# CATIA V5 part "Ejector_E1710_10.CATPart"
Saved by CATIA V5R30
Part number: Vyhazovac_2.5x160_8
Nomenclature: E1710/2.5x160
Description: MEUSBURGER
Property "Material": "1.221"
Publications: "__DrillHole", "Base"
Bounding box of the stored display mesh (mm): x -2.499 to 2.499, y -2.499 to 2.499, z 0 to 154.3
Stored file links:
  E:\Bakalarka\Model\Forma_v7\Ejector_E1710_10.CATPart
  E:\dev\MoldDesign\intel_a\startup\components\MoldCatalog\Ejector\Meusburger\Ejector_E1710\TableE1710.txt
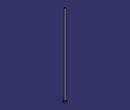
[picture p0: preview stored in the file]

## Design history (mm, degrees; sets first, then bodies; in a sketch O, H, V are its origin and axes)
Parameters
  Ref = "E1710/2.5x160" {design table}
  D1 = 2.5 mm {design table}
  D3 = 5 mm {design table}
  L = 160 mm {design table}
  L3 = 2 mm {design table}
  R = 0.3 mm {design table}
  k_d3 = 6 mm {design table}
  k_d1 = 2.7 mm {design table}
  k_F = 0.3 mm {design table}
  kl = 17 mm {design table}
  Mat = "1.221" {design table}
  HeatTreat = "ISO6751" {design table}
  Offset_Parting = 10 mm
  Anti_Rotation = "Normal"
  Anti_Rotation_D = 1.55 mm
  Anti_Rotation_D_Icut = 1.55 mm
  Add_Length_L = 0.0877 mm
  Add_Length_D3 = 0 mm
  SupplierRef = "Meusburger 2017"
  BmpRef = "F_MldEjectorD1"
  DrillHole_Length = 225 mm
  ValidationTest = false
  Anti_Rotation_D_min = 1.55 mm {= OffSet_D1 /2}
  Anti_Rotation_D_max = 2.425 mm {= D3/2-0.075mm}
  Anti_Rotation_D_ref = 1.55 mm {= Anti_Rotation_D}
  Anti_Rotation_D_Icut_ref = 1.55 mm {= Anti_Rotation_D_Icut}
  Anti_Rotation_Ref_Icut = 2.3246 mm
  Offset_L = 20 mm
  D = 2.5 mm {= D1}
  OffSet_D1 = 3.1 mm {= D1+2*R}
  OffSet_D3 = 6 mm {= D3+1mm}
  XG_Split = 60 mm
  YG_Split = -57.5 mm
  ZG_Split = -198 mm
  DirX_Split = 0 mm
  DirY_Split = 0 mm
  DirZ_Split = 1 mm
Set1 "BaseBody"
  Point1 "Base": (0, 0, 0)
  Plane1: type Offset, RefPlane xy-plane, Offset 225 {= DrillHole_Length}, reversed
  Sketch1 "Sketch.2" on xy-plane, origin (0, 0, 0), H (1, 0, 0), V (0, 1, 0)
    point P1 (-0.46, 1.1623)
    point P2 (0.46, 1.1623)
    construction line L1 (-0.46, 1.1623) -> (0.46, 1.1623)
    point P3 (0.46, -1.1623)
    line L2 (0.46, -1.1623) -> (0.46, 1.1623)
    point P4 (-0.46, -1.1623)
    construction line L3 (0.46, -1.1623) -> (-0.46, -1.1623)
    line L4 (-0.46, 1.1623) -> (-0.46, -1.1623)
    point P5 (-0.21, 1.1623)
    arc A1 centre (-0.21, 1.1623) radius 0.25 from (-0.21, 1.4123) to (-0.46, 1.1623) ccw
    point P7 (0.21, 1.1623)
    point P8 (0.21, 1.4123)
    arc A2 centre (0.21, 1.1623) radius 0.25 from (0.46, 1.1623) to (0.21, 1.4123) ccw
    line L5 (-0.21, 1.4123) -> (0.21, 1.4123)
    point P9 (-0.46, -1.1623)
    arc A3 centre (-0.21, -1.1623) radius 0.25 from (-0.46, -1.1623) to (-0.21, -1.4123) ccw
    point P11 (0.21, -1.4123)
    line L6 (-0.21, -1.4123) -> (0.21, -1.4123)
    point P12 (0.46, -1.1623)
    arc A4 centre (0.21, -1.1623) radius 0.25 from (0.21, -1.4123) to (0.46, -1.1623) ccw
    point P14 (-0.46, 1.1623)
    point P15 (-0.46, -1.1623)
    point P16 (0.46, 1.1623)
    point P17 (0.46, -1.1623)
    reference projected circle E1 centre (0, 0) radius 1.25 from edge [face of Shaft1 from Sketch2.L3 | face of Shaft1 from Sketch2.L4]
    reference projected circle E2 centre (0, 0) radius 1.25 from edge [face of Shaft1 from Sketch2.L3 | face of Shaft1 from Sketch2.L4]
    reference projected circle E3 centre (0, 0) radius 1.25 from edge [face of Shaft1 from Sketch2.L3 | face of Shaft1 from Sketch2.L4]
    reference projected circle E4 centre (0, 0) radius 1.25 from edge [face of Shaft1 from Sketch2.L3 | face of Shaft1 from Sketch2.L4]
    point P18 (-0.46, -1.1623)
    point P19 (-0.21, -1.4123)
    point P20 (0.21, -1.4123)
    point P21 (0.46, -1.1623)
    point P22 (-0.21, -1.4123)
    point P23 (0.21, -1.4123)
    distance P14 P15 = 2.3246 (reference)
    distance P16 P17 = 2.3246 (reference)
    distance L1 P14 = 0 (reference)
    radius A1 = 1.25
    distance L4 V = 1.56
    distance L2 V = 2.435
    distance L5 L6 = 5
    horizontal: L1 H, L3 H, L5 H
    vertical: L2 V, L4 V
    coincidence: P5 L1, P7 L1, P3 P12, P14 L4, P15 L4, P16 L2, P17 L2, P14 E1, P15 E2, P16 E3, P17 E4, P3 P21, P4 P18, P20 P23, P19 P22
    tangency: A1 L4, A2 L2, A2 L5, A1 L5
    symmetry: P1 P9 H, A1 A3 H, P8 P11 H, L5 L6 H, P2 P12 H, A2 A4 H
  DatumSurface1
Body1 "PartBody" (main body)
  Sketch2 "Sketch.1" on zx-plane, origin (0, 0, 0), H (-1, 0, 0), V (0, 0, 1)
    point P1 (0, 160)
    line L1 (1.25, 160) -> (0, 160)
    line L2 (1.25, 2) -> (1.25, 160)
    line L3 (2.5, 2) -> (1.25, 2)
    line L4 (2.5, 0) -> (2.5, 2)
    point P5 (0, 0)
    line L5 (0, 0) -> (2.5, 0)
    point P6 (0, 160)
    axis line L6 (0, 160) -> (0, 0)
    point P7 (0, 0)
    point P8 (1.25, 2)
    point P9 (1.25, 2)
    line L7 (0, 160) -> (0, 0)
    distance L5 L3 = 2 {= L3}
    distance L5 L1 = 160 {= L}
    distance L2 L6 = 1.25 {= D1 /2}
    distance L4 L6 = 2.5 {= D3 /2}
    coincidence: L6 P5, P1 L6, L5 H, L6 V, P7 O, P6 P1, P8 P9
    vertical: L2 V, L7 V
    horizontal: L1 H
  Shaft1 "Shaft.1": profile Sketch2, axis Sketch2.L6, angle 360
  Pocket1 "Pocket.1": profile Sketch1, direction (0, 0, 1), length 3, outer side, deactivated
  Pocket2 "Pocket.2": profile Sketch1, direction (0, 0, 1), length 3, outer side, deactivated
  Fillet1: radius 0.3 {= R}, on edge [face of Shaft1 from Sketch2.L2 | face of Shaft1 from Sketch2.L3]
  Pocket3: profile face of Shaft1 from Sketch2.L1, direction along face of Shaft1 from Sketch2.L1 reversed, up to face of DatumSurface1
Body2 "__DrillHole"
  Sketch3 "Sketch.3" on face of Shaft1, origin (0, 0, 0), H (1, 0, 0), V (0, -1, 0)
    point P1 (0, 0)
    reference projected point E1 (0, 0) from Point1
    coincidence: E1 P1
  Hole1 "Hole.1": placed by Sketch3, at (0, 0, 0) direction (0, 0, 1), diameter 3.1 {= OffSet_D1}, depth 140 {= L-Offset_L}
  Sketch4 "Sketch.4" on face of Shaft1, origin (0, 0, 0), H (1, 0, 0), V (0, -1, 0)
    point P1 (0, 0)
    reference projected point E1 (0, 0) from Point1
    coincidence: E1 P1
  Hole2 "Hole.2": placed by Sketch4, at (0, 0, 0) direction (0, 0, 1), diameter 2.5 {= D1}, depth 160 {= L}
  Sketch5 "Sketch.5" on face of Shaft1 from Sketch2.L3, origin (0, 0, 2), H (1, 0, 0), V (0, 1, 0)
    point P1 (0, 0)
    reference projected point E1 (0, 0) from Point1
    coincidence: E1 P1
  Hole3 "Hole.3": placed by Sketch5, at (0, 0, 2) direction (0, 0, -1), diameter 6 {= OffSet_D3}, depth 227 {= L3 +DrillHole_Length}
  Chamfer1: length 0.3 {= k_F}, angle 45, on edge [face of Hole1 | face of Hole3]
  Body3 "__Body.1"
    Pocket4 "Pocket.3": profile Sketch1, direction (0, 0, -1), length 225, opposite side length 2, deactivated
  Assemble1: tool Body3
  Chamfer2: length 0.3 {= k_F}, angle 45, on edge [start face of Pocket4 | face of Hole1], deactivated
  Body4 "__Body.2"
    Pocket5 "Pocket.4": profile Sketch1, direction (0, 0, -1), length 225, opposite side length 2, deactivated
  Assemble2: tool Body4
  Chamfer3: length 0.3 {= k_F}, angle 45, on edge [start face of Pocket5 | face of Hole1], deactivated
Relations
  design table "TableE1710", configuration 134, drives Ref, D1, D3, L, L3, R, k_d3, k_d1, k_F, kl, Mat, HeatTreat
  Offset_L = 20mm (deactivated)
  rule "Cut_Head_rule":
    let sketch_cut (length)
    let PartBody_Pocket_Sketch (Boolean)
    let I_PartBody_Pocket (Boolean)
    let D_PartBody_Pocket (Boolean)
    let N_DrillHole_Hole (Boolean)
    let N_DrillHole_Hole_Sketch (Boolean)
    let I_DrillHole_Pocket (Boolean)
    let D_DrillHole_Pocket (Boolean)
    /* --------------------------------------------------------------------------------------*/
    if Anti_Rotation =="Normal"
    {
    	sketch_cut=Anti_Rotation_D_max
    	PartBody_Pocket_Sketch = false
    	I_PartBody_Pocket = false
    	D_PartBody_Pocket = false
    	N_DrillHole_Hole = true
    	N_DrillHole_Hole_Sketch = true
    	I_DrillHole_Pocket = false
    	D_DrillHole_Pocket = false
    	Chamfer1.Activity= true
    	Chamfer2.Activity= false
    	Chamfer3.Activity= false
    }
    if Anti_Rotation == "I_Cut"
    {
    	sketch_cut=Anti_Rotation_D_Icut_ref
    	PartBody_Pocket_Sketch = true
    	I_PartBody_Pocket = true
    	D_PartBody_Pocket = false
    	N_DrillHole_Hole = false
    	N_DrillHole_Hole_Sketch = false
    	I_DrillHole_Pocket = true
    	D_DrillHole_Pocket = false
    	Chamfer1.Activity= false
    	Chamfer2.Activity= true
    	Chamfer3.Activity= false
    }
    if Anti_Rotation =="D_Cut"
    {
    	sketch_cut=Anti_Rotation_D_max
    	PartBody_Pocket_Sketch = true
    	I_PartBody_Pocket = false
    	D_PartBody_Pocket = true
    	N_DrillHole_Hole = false
    	N_DrillHole_Hole_Sketch = false
    	I_DrillHole_Pocket = false
    	D_DrillHole_Pocket = true
    	Chamfer1.Activity= false
    	Chamfer2.Activity= false
    	Chamfer3.Activity= true
    }
    /* --------------------------------------------------------------------------------------*/
    Sketch1.distance(L2 V) = sketch_cut+0.01mm
    Sketch1.distance(L4 V) =Anti_Rotation_D_ref+0.01mm
    Sketch1.radius(A1) =D/2
    Pocket4.FirstLimit.Depth = DrillHole_Length
    Pocket5.FirstLimit.Depth = DrillHole_Length
    Pocket1.FirstLimit.Depth = L3+1mm
    Pocket2.FirstLimit.Depth = L3+1mm
    Pocket4.SecondLimit.Depth = L3
    Pocket5.SecondLimit.Depth =L3
    Pocket1.Activity = I_PartBody_Pocket
    Pocket2.Activity = D_PartBody_Pocket
    Sketch1.Activity =PartBody_Pocket_Sketch
    Hole3.Activity= N_DrillHole_Hole
    Sketch5.Activity = N_DrillHole_Hole_Sketch
    Pocket4.Activity = I_DrillHole_Pocket
    Pocket5.Activity  = D_DrillHole_Pocket
  rule "Anti_Rotation_Icut_constrain":
    let Ref1(length)
    let Ref2(length)
    let Ref3(length)
    let Diam1(length)
    let Diam2(length)
    let Add_Length_Lmin (length)
    Ref1=Sketch1.distance(P14 P15)
    Ref2=Sketch1.distance(P16 P17)
    Diam1=D
    Diam2=D3
    /* --------------------------------------------------------------------*/
    if Ref1 >Ref2
    	Anti_Rotation_Ref_Icut = Ref1
    else
    	Anti_Rotation_Ref_Icut  =Ref2
    Add_Length_D3 .InferiorRange=Anti_Rotation_Ref_Icut /2+Diam1/2 -Diam2/2
    if Add_Length_D3 .InferiorRange<0mm
    	Add_Length_D3 .InferiorRange=0mm
    if ValidationTest == "true"
    	Ref3   = 2*Add_Length_L +Anti_Rotation_Ref_Icut  +2*Diam1/2
    else
    	Ref3  =Diam2+2*Add_Length_D3
    if Ref3 <Diam2
    {
    	Ref3 =Diam2
    }
    /* --------------------------------------------------------------------*/
    Sketch1.distance(L5 L6) = Ref3
    Add_Length_L .InferiorRange=Diam2/2-Anti_Rotation_Ref_Icut/2-Diam1/2
    Add_Length_Lmin=Diam2/2-Anti_Rotation_Ref_Icut/2-Diam1/2
    if Add_Length_Lmin<0mm
    	Add_Length_L .InferiorRange=0mm
    else
    	Add_Length_L .InferiorRange=Add_Length_Lmin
